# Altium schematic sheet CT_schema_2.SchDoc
size 276 x 169 mm
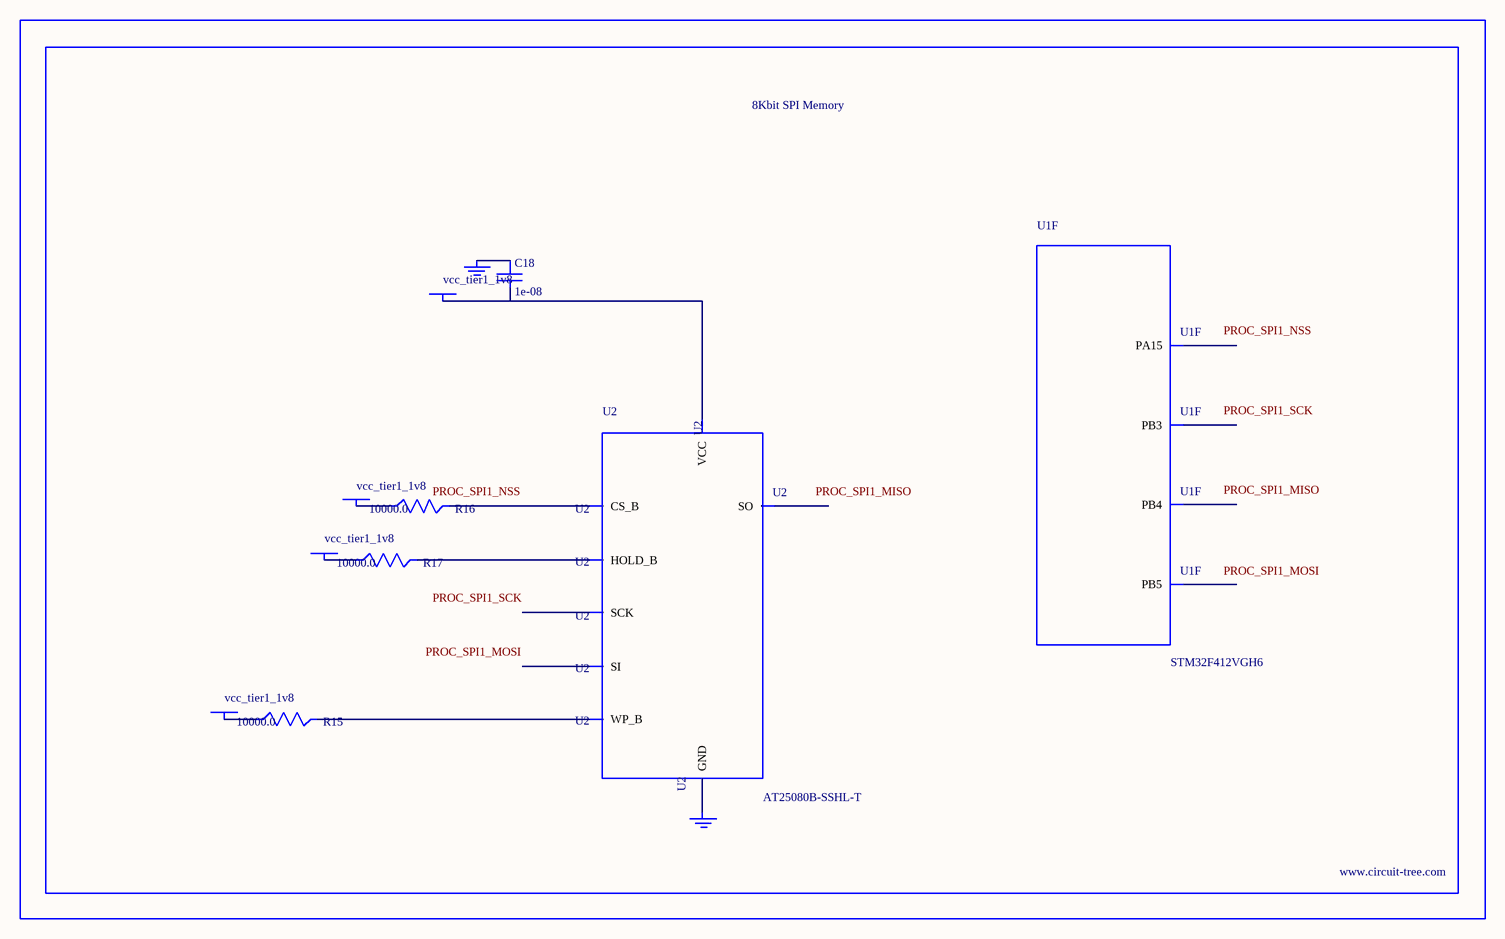
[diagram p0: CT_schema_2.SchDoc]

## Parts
BORDER1  (no value)
C18  1e-08  [C0402]
GND_INSTANCE_1_0  (no value)
GND_INSTANCE_1_1  (no value)
POWER_INSTANCE_1_0  vcc_tier1_1v8
POWER_INSTANCE_1_1  vcc_tier1_1v8
POWER_INSTANCE_1_2  vcc_tier1_1v8
POWER_INSTANCE_1_3  vcc_tier1_1v8
R15  10000.0  [R0603]
R16  10000.0  [R0603]
R17  10000.0  [R0603]
U1  STM32F412VGH6  [UFBGA100]  (part F of 11)
U2  AT25080B-SSHL-T  [SOIC-8]

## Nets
NetC18_1: C18.1 GND_INSTANCE_1_0.0(GND)
NetC18_2: C18.2 POWER_INSTANCE_1_3.0(PWR) U2.8(VCC)
NetGND_INSTANCE_1_1_0: GND_INSTANCE_1_1.0(GND) U2.4(GND)
NetPOWER_INSTANCE_1_0_0: POWER_INSTANCE_1_0.0(PWR) R16.1
NetPOWER_INSTANCE_1_1_0: POWER_INSTANCE_1_1.0(PWR) R15.1
NetPOWER_INSTANCE_1_2_0: POWER_INSTANCE_1_2.0(PWR) R17.1
NetR15_2: R15.2 U2.3(WP_B)
NetR16_2: R16.2 U2.1(CS_B)
NetR17_2: R17.2 U2.7(HOLD_B)

Not connected (* = marked no-connect by the designer): U1 A7(PB4) A8(PB3) A9(PA15) C5(PB5); U2 2(SO) 5(SI) 6(SCK)

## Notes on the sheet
- Labels drawn without touching a wire or pin: PROC_SPI1_MISO, PROC_SPI1_MOSI, PROC_SPI1_NSS, PROC_SPI1_SCK

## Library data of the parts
BORDER1 = BORDER_PAGE1
C18 = C0402C103K3RAC
GND_INSTANCE_1_0 GND_INSTANCE_1_1 = GND
POWER_INSTANCE_1_0-POWER_INSTANCE_1_3 = PWR
R15-R17 = RC0603JR-0710KL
